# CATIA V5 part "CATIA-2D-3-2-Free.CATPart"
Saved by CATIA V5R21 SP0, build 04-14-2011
Part number: CATIA-2D-3-2-Free
Bounding box of the stored display mesh (mm): x -78.859 to 78.843, y -1 to 1, z -27 to 139.993
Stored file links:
  C:\Users\Rasoul Mohammadi\Desktop\CATIA-Free\2D\CATIA-2D-3-2-Free.CATPart
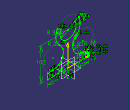
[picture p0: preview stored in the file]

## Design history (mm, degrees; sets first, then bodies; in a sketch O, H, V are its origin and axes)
Body1 (main body)
  Sketch1 on zx-plane, origin (0, 0, 0), H (-1, 0, 0), V (0, 0, 1)
    line L1 (-63.5, 0) -> (-29.5127, 0)
    point P1 (-63.5, 0)
    point P2 (63.5, 0)
    arc A1 centre (0, 102) radius 25 from (-21.6506, 114.5) to (21.6506, 114.5) ccw
    point P3 (0, 102)
    arc A2 centre (0, 102) radius 38 from (-32.909, 121) to (-25.4391, 73.7714) ccw
    construction line L2 (0, 102) -> (21.6506, 114.5)
    point P4 (32.909, 121)
    line L3 (63.5, 0) -> (63.5, 8)
    point P5 (63.5, 18)
    line L4 (53.5, 18) -> (46.8615, 18)
    point P6 (46.8615, 18)
    point P7 (21.6506, 114.5)
    line L5 (21.6506, 114.5) -> (32.909, 121)
    point P8 (-32.909, 121)
    point P9 (-21.6506, 114.5)
    line L6 (-21.6506, 114.5) -> (-32.909, 121)
    arc A3 centre (46.8615, 50) radius 32 from (25.4391, 73.7714) to (46.8615, 18) ccw
    point P11 (25.4391, 73.7714)
    axis line L7 (0, 102) -> (38, 102)
    point P12 (38, 102)
    arc A4 centre (53.5, 8) radius 10 from (63.5, 8) to (53.5, 18) ccw
    point P13 (63.5, 8)
    point P14 (53.5, 18)
    point P16 (-63.5, 0)
    point P17 (-63.5, 18)
    point P18 (-46.8615, 18)
    point P20 (-25.4391, 73.7714)
    point P21 (-63.5, 8)
    point P22 (-53.5, 18)
    line L8 (-63.5, 0) -> (-63.5, 8)
    line L9 (-53.5, 18) -> (-46.8615, 18)
    arc A5 centre (-46.8615, 50) radius 32 from (-25.4391, 73.7714) to (-46.8615, 18) cw
    arc A6 centre (-53.5, 8) radius 10 from (-63.5, 8) to (-53.5, 18) cw
    arc A7 centre (0, 102) radius 38 from (25.4391, 73.7714) to (32.909, 121) ccw
    arc A8 centre (0, -27) radius 40 from (29.5127, 0) to (-29.5127, 0) ccw
    point P24 (0, -27)
    point P26 (29.5127, 0)
    line L10 (29.5127, 0) -> (63.5, 0)
    distance P3 L1 = 102
    radius A1 = 25
    radius A2 = 38
    angle L7 L2 = 30
    radius A3 = 32
    distance P2 P5 = 18
    radius A4 = 10
    distance P1 P2 = 127
    radius A8 = 40
    distance A8 L10 = 13
    coincidence: P1 H, P3 V, L2 L5, P11 A2, P12 A2, L3 P5, L4 P5, A2 A7, P24 V, L1 P26, L1 L10
    horizontal: L1 H, L4 H, L7 H, L10 H
    symmetry: P2 P1 V, P4 P8 V, P7 P9 V, L5 L6 V, P2 P16 V, P5 P17 V, P6 P18 V, P11 P20 V, P13 P21 V, P14 P22 V, L3 L8 V, L4 L9 V, A3 A5 V, A4 A6 V
    vertical: L3 V
    tangency: A3 A2, L4 A3, A4 L3, A4 L4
